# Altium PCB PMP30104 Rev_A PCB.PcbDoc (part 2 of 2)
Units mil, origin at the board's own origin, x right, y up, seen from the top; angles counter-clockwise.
Board outline 1835 x 2150 mil, 2 copper layers (Top Layer, Bottom Layer), stack 62 mil thick; 81 components, 42 nets, 182 pads, 76 vias.
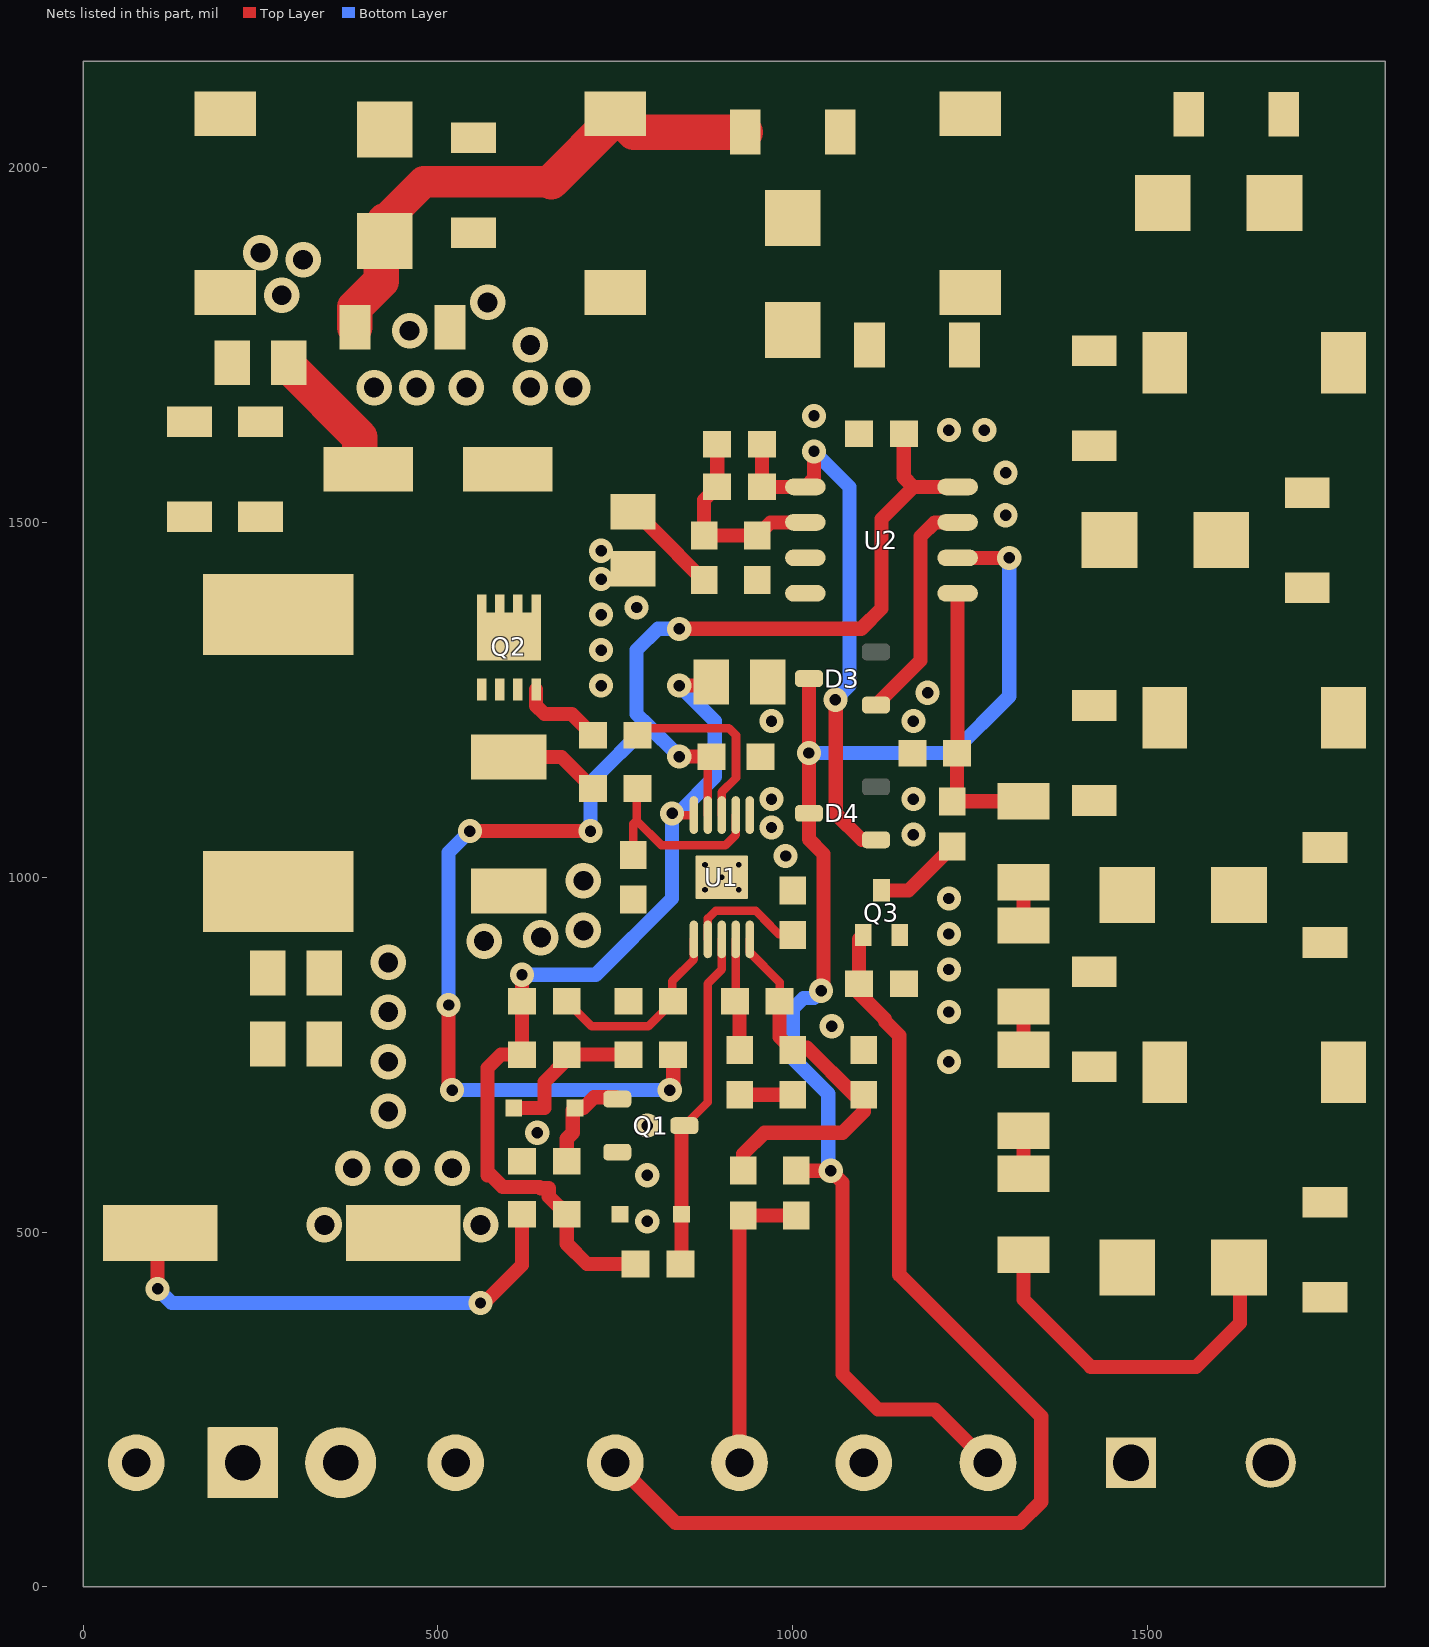
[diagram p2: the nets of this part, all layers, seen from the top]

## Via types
v1: diameter 34, hole 16, Top Layer to Bottom Layer, 47 vias
v2: diameter 50, hole 28, Top Layer to Bottom Layer, 24 vias
v3: diameter 19.68, hole 7.87, Top Layer to Bottom Layer, 5 vias

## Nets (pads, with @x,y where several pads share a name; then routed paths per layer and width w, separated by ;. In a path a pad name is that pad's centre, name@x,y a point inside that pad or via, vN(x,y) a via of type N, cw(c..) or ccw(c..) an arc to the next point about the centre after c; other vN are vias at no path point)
8VBIAS: C10.1 C15.2 R1.2 U1.9 U2.8 | length 2097.9
  Top Layer w12: U1.9@880.31,1087.6 880.31,1164.81 C10.1@885.5,1170
  Top Layer w20: v1(515,820) 515,705 v1(520,700) ; v1(545,1065) v1(715,1065) ; v1(826.57,700) 831.5,704.92 R1.2@831.5,750 ; v1(840,1170) C10.1@885.5,1170 ; v1(840,1350) 1096.38,1350 1124.92,1378.54 1124.92,1504.92 1170,1550 ; C15.2@1156.5,1625 1156.5,1563.5 1170,1550 ; U2.8@1232.28,1550 1170,1550
  Bottom Layer w20: v1(515,820) 515,1035 v1(545,1065) ; v1(520,700) v1(826.57,700) ; v1(715,1065) 715,1133.5 795.75,1214.25 ; v1(840,1170) 795.75,1214.25 ; v1(840,1350) 810,1350 780,1320 780,1230 795.75,1214.25
400V-420V: Q3.1 R24.1 TP8.1 | length 1554.8
  Top Layer w20: TP8.1@750,175 835,90 1320,90 1350,120 1350,240 1150,440 1150,777.04 1130,797.04 1130,800 1093.5,836.5 R24.1@1093.5,850 1093.5,912.6 Q3.1@1099.41,918.5
CS: D3.3 D4.3 R10.2 TP5.1 U2.6 | length 1932.7
  Top Layer w20: R10.2@1005,586.5 v1(1053.5,586.5) 1070,570 1070,300 1120,250 1200,250 TP5.1@1275,175 ; D3.3@1022.76,1280 v1(1022.76,1175) D4.3@1022.76,1090 1022.76,1053.57 1043.43,1032.9 1043.43,843.43 v1(1040,840) ; U2.6@1232.28,1450 v1(1305,1450)
  Bottom Layer w20: v1(1022.76,1175) 1225,1175 1305,1255 v1(1305,1450) ; v1(1040,840) 1030,830 1015,830 1000,815 1000,745 1050,695 1050,590 v1(1053.5,586.5)
GND: C1.2 C2.2 C4.2 C6.2 C7.2 C8.2 C9.2 C10.2 C14.1 C15.1 Cm6.1 D2.2 J1.2 J2.1 Q1.2 Q3.2 R3.1 R5.1 R13.1 R14.1 R21.2 R24.2 TP2.1 TP4.1 U1.6 U1.11 U2.3 U2.4
  other v1: 795,515 795,580 640,640 795,650 1220,740 1055,790 1220,810 1220,870 1220,920 1220,970 990,1030 1170,1060 970,1070 970,1110 1170,1110 970,1220 1170,1220 1190,1260 730,1270 730,1320 730,1370 780,1380 730,1420 730,1460 1300,1510 1300,1570 1220,1630 1270,1630 1030,1650
  other v2: 340,510 560,510 380,590 450,590 520,590 430,670 430,740 430,810 430,880 565,910 645,915 705,925 705,995 410,1690 470,1690 540,1690 460,1770 570,1810
  other v3: 876.38,982.28 923.62,982.28 900,1000 876.38,1017.72 923.62,1017.72
NetC1_1: C1.1 R7.1 U1.1 | length 279.7
  Top Layer w12: R7.1@681.5,825 716.5,790 796.5,790 C1.1@831.5,825 830,826.5 830,853.54 860.63,884.17 U1.1@860.63,912.4
NetC2_1: C2.1 U1.2 | length 168.4
  Top Layer w12: U1.2@880.31,912.4 880.24,941.96 891.75,952.98 947.62,952.98 959.28,941.32 959.28,940.72 980,920 998.5,920 C2.1@1000,918.5
NetC3_1: C3.1 C5.1 U1.4 | length 159.1
  Top Layer w12: C3.1@918.5,825 919.68,826.18 U1.4@919.68,912.4
  Top Layer w20: C3.1@918.5,825 925,818.5 C5.1@925,756.5
NetC3_2: C3.2 R5.2 R6.2 R8.1 U1.5 | length 551.9
  Top Layer w12: U1.5@939.37,912.4 939.37,894.17 981.5,852.05 C3.2@981.5,825
  Top Layer w20: R8.1@930,586.5 930,610 960,640 1070,640 1100,670 R5.2@1100,693.5 1086.5,693.5 1020,760 1003.5,760 R6.2@1000,756.5 981.5,775 C3.2@981.5,825
NetC4_1: C4.1 C6.1 C7.1 J1.1 L1.1 R9.2 TP1.1 | length 696
  Top Layer w20: C4.1@103.74,500 105,498.74 v1(105,420) ; v1(560,400) 565,400 618.5,453.5 R9.2@618.5,525
  Bottom Layer w20: v1(105,420) 125,400 v1(560,400)
NetC5_2: C5.2 R6.1 | length 75
  Top Layer w20: C5.2@925,693.5 R6.1@1000,693.5
NetC8_1: C8.1 R2.2 R4.2 R7.2 R9.1 U1.10 | length 1296.4
  Top Layer w12: v1(830,1090) 832.4,1087.6 U1.10@860.63,1087.6
  Top Layer w20: v1(618.5,862.5) R7.2@618.5,825 R2.2@618.5,750 588.98,750 570,731.02 570,580 574.66,580 591.36,563.3 643.2,563.3 644.8,561.7 656.19,561.7 656.19,550.31 R9.1@681.5,525 681.5,483.5 710,455 R4.2@778.5,455 ; v1(840,1270) 880,1270 C8.1@885,1275
  Bottom Layer w20: v1(618.5,862.5) 722.5,862.5 830,970 v1(830,1090) 838.54,1090 890,1141.46 890,1220 v1(840,1270)
NetC9_1: C9.1 R12.1 U1.7 | length 284.4
  Top Layer w12: C9.1@775,1031.5 775,1075 780,1080 ; R12.1@781.5,1125 780,1123.5 780,1080 ; U1.7@919.68,1087.6 919.68,1059.68 905,1045 815,1045 780,1080
NetC11_1: C11.1 C12.1 Cm1.1 Dm1.2 Lm1.1 R23.2
NetC11_2: C11.2 C12.2 C16.1 L1.2 Q2.5 Q2.6 Q2.7 Q2.8 Q2.9
NetC13_1: C13.1 C14.2 R19.1 R20.2 U2.2 | length 276.5
  Top Layer w20: C13.1@893.5,1600 R19.1@893.5,1550 875,1531.5 R20.2@875,1481.5 C14.2@950,1481.5 968.5,1500 U2.2@1017.72,1500
NetC13_2: C13.2 D4.1 R19.2 U2.1 | length 778
  Top Layer w20: C13.2@956.5,1600 R19.2@956.5,1550 U2.1@1017.72,1550 1030,1562.28 v1(1030,1600) ; v1(1060,1250) 1060.44,1249.56 1060.44,1089.56 1097.4,1052.6 D4.1@1117.24,1052.6
  Bottom Layer w20: v1(1030,1600) 1080,1550 1080,1270 v1(1060,1250)
NetC16_2: C16.2 R23.1 | length 196.2
  Top Layer w50: R23.1@290,1725 290,1720 390,1620 390,1586.57 C16.2@401.57,1575
NetCm1_2: Cm1.2 Cm2.1 Dm2.2 Lm2.1
NetCm2_2: Cm2.2 Cm3.1 Dm3.2 Lm3.1
NetCm3_2: Cm3.2 Cm4.1 Dm4.2 Lm4.1
NetCm4_2: Cm4.2 Cm5.1 Dm5.2 Lm5.1
NetCm5_2: Cm5.2 Dm6.2 Lm6.1
NetCm6_2: Cm6.2 Cm7.1 Dm1.1 Lm2.2 | length 745.2
  Top Layer w45: Dm1.1@425,1925 480,1980 660,1980
  Top Layer w50: Cm6.2@383.07,1775 383.07,1803.07 420,1840 Dm1.1@420,1891.26 ; Dm1.1@425,1896.26 Dm1.1@425,1925 ; 660,1980 750,2070 Lm2.2@750,2075.98 775.98,2050 Cm7.1@933.07,2050
NetCm7_2: Cm7.2 Cm8.1 Dm2.1 Lm3.2
NetCm8_2: Cm8.2 Cm9.1 Dm3.1 Lm4.2
NetCm9_2: Cm9.2 Cm10.1 Dm4.1 Lm5.2
NetCm10_2: Cm10.2 Cm11.1 Dm5.1 Lm6.2
NetCm11_2: Cm11.2 Dm6.1 J2.2 R18.1 | length 511.6
  Top Layer w20: R18.1@1325,467.91 1325,405 1420,310 1568.15,310 1630,371.85 1630,448.74 Dm6.1@1628.74,450
NetD1_1: D1.1 R1.1 R2.1 | length 218.4
  Top Layer w20: D1.1@606.69,675 650,675 650,711.47 681.5,742.97 R2.1@681.5,750 R1.1@768.5,750
NetD1_2: D1.2 Q1.1 R3.2 | length 146.6
  Top Layer w20: R3.2@681.5,600 681.5,631.5 690,640 690,671.69 D1.2@693.31,675 705,675 720,690 750.16,690 Q1.1@752.76,687.4
NetD2_1: D2.1 Q1.3 R4.1 U1.3 | length 481.6
  Top Layer w12: Q1.3@843.31,646.06 Q1.3@847.24,650 880,682.76 880,850 900,870 U1.3@900,912.4
  Top Layer w20: R4.1@841.5,455 843.31,456.81 D2.1@843.31,525 Q1.3@843.31,646.06
NetD3_1: D3.1 U2.7 | length 324
  Top Layer w20: D3.1@1117.24,1242.6 1180,1305.35 1180,1480 1200,1500 U2.7@1232.28,1500
NetLm1_2: Lm1.2 R20.1 R21.1 | length 140.5
  Top Layer w20: R21.1@775,1515 778.5,1515 838.3,1455.2 838.3,1454.36 874.15,1418.5 R20.1@875,1418.5
  other v2: 630,1690 690,1690 630,1750 280,1820 310,1870 250,1880
NetQ2_1: Q2.1 Q2.2 Q2.3 R12.2 R13.2 | length 136.9
  Top Layer w20: R13.2@600,1169.49 674.02,1169.49 R12.2@718.5,1125
NetQ2_4: Q2.4 R11.2 | length 120.2
  Top Layer w20: Q2.4@638.39,1264.47 638.39,1241.61 650,1230 688.5,1230 R11.2@718.5,1200
NetQ3_3: Q3.3 R22.1 | length 125.7
  Top Layer w20: Q3.3@1125,981.5 1162.99,981.5 R22.1@1225,1043.5
NetR8_2: R8.2 R10.1 TP3.1 | length 425.6
  Top Layer w20: TP3.1@925,175 925,518.5 R8.2@930,523.5 R10.1@1005,523.5
NetR11_1: R11.1 U1.8 | length 267.5
  Top Layer w12: R11.1@781.5,1200 791.5,1210 910,1210 920,1200 920,1140 900,1120 U1.8@900,1087.6
NetR14_2: R14.2 R15.2 R22.2 U2.5 | length 395.9
  Top Layer w20: R22.2@1225,1106.5 R22.2@1225.59,1107.09 ; U2.5@1232.28,1400 1232.28,1175.79 R14.2@1231.5,1175 1231.5,1112.99 R22.2@1225.59,1107.09 ; R15.2@1325,1107.09 R22.2@1225.59,1107.09
NetR15_1: R15.1 R16.2 | length 60.8
  Top Layer w20: R16.2@1325,932.09 R15.1@1325,992.91
NetR16_1: R16.1 R17.2 | length 60.8
  Top Layer w20: R17.2@1325,757.09 R16.1@1325,817.91
NetR17_1: R17.1 R18.2 | length 60.8
  Top Layer w20: R18.2@1325,582.09 R17.1@1325,642.91
pads on no net: D3.2 D4.2

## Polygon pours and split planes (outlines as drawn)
NetCm11_2 on Top Layer "Top Layer-No Net 11" (solid, pour order 24): 1573.43,503.43 1590,520 1660,520 1690,490 1700,480 1790,480 1810,460 1810,130 1760,80 1645,80 1645,270 1573.43,330
NetCm5_2 on Top Layer "Top Layer-No Net 10" (solid, pour order 22): 1390,800 1570,800 1590,780 1590,570 1530,510 1530,421.5 1500,391.5 1418.5,391.5 1410,400 1390,420
NetCm10_2 on Top Layer "Top Layer-No Net 8" (solid, pour order 20): 1580,1010 1590,1020 1643.5,1020 1690,973.5 1690,970 1790,970 1810,950 1810,520 1800,510 1712.6,510 1702.6,520 1700,520 1700,570 1630,640 1630,650 1630,850 1580,910
NetCm4_2 on Top Layer "Top Layer-No Net 9" (solid, pour order 18): 1490,1270 1500,1280 1590,1280 1600,1270 1600,1080.12 1560.5,1040.62 1560.5,1033.5 1550,1023 1550,940 1540,930 1530,930 1510,910 1510,880 1470,840 1462.4,840 1390,840 1390,1190 1462.4,1190 1470,1190 1490,1210
NetCm9_2 on Top Layer "Top Layer-No Net 8" (solid, pour order 16): 1550,1510 1570,1530 1570,1533.5 1630,1533.5 1690,1473.5 1690,1470 1790,1470 1810,1450 1810,1020 1800,1010 1712.6,1010 1702.6,1020 1700,1020 1700,1070 1630,1140 1630,1150 1630,1350 1550,1430 1550,1440
NetCm3_2 on Top Layer "Top Layer-No Net 7" (solid, pour order 14): 1490,1800 1590,1800 1600,1790 1600,1780 1600,1610 1510,1520 1510,1430 1510,1380 1460,1330 1460,1230 1450,1220 1440,1220 1370,1220 1365,1225 1365,1655 1370,1660 1390,1660 1470,1660 1490,1680
NetCm8_2 on Top Layer "Top Layer-No Net 6" (solid, pour order 12): 1640,2120 1810,2120 1810,1520 1800,1510 1790,1510 1700,1510 1640,1570 1640,1580
NetCm2_2 on Top Layer "Top Layer-No Net 5" (solid, pour order 10): 1180,1910 1390,1910 1470,1990 1590,1990 1590,1850 1570,1830 1560,1830 1470,1830 1460,1820 1462.4,1817.6 1462.4,1710 1452.4,1700 1450,1700 1180,1700
NetCm7_2 on Top Layer "Top Layer-No Net 4" (solid, pour order 8): 1010,2130 1590,2130 1600,2120 1600,2112.4 1600,2037.6 1592.4,2030 1590,2030 1450,2030 1370,1950 1170,1950 1140,1950 1080,1890 960,1890 940,1910 940,1972 938,1974 994,2030 1000,2036 1000,2120
NetCm1_2 on Top Layer "Top Layer-No Net 3" (solid, pour order 6): 520,1930 870,1930 990,1810 1100,1810 1130,1810 1140,1800 1140,1790 1140,1710 1130,1700 930,1700 850,1780 690,1780 600,1870 520,1870
NetC11_1 on Top Layer "Top Layer-No Net 2" (solid, pour order 4): 20,2130 610,2130 609.06,2129.06 609.06,2020 560,2020 470,2020 440,1990 350,1990 290,1930 150,1930 130,1910 130,1780 140,1770 145,1765 230,1765 240,1755 240,1750 250,1740 250,1670 280,1670 290,1660 287.4,1657.4 287.4,1610 20,1610
NetC11_2 on Top Layer "Top Layer-No Net 1" (solid, pour order 2): 30,1580 310,1580 310,1530 320,1520 480,1520 490,1530 490,1540 490,1630 500,1640 700,1640 700,1300 533.07,1300 503.07,1270 500,1270 510,1260 510,1140 490,1120 30,1120
NetC4_1 on Top Layer "Top Layer-No Net" (solid, pour order 0): 10,100 280,100 280,120 280,900 280,920 430,920 460,950 460,1060 440,1080 440,1090 10,1090
NetQ2_1 on Top Layer "Top Layer-No Net 12" (solid, pour order 26): 533.07,1270 543.07,1280 550,1280 620,1280 620,1230 650,1200 660,1200 670,1200 680,1190 680,1180 706.46,1153.54 740,1153.54 740,1096.46 723.54,1080 710,1080 540,1080 530,1090 530,1100 530,1270
NetLm1_2 on Top Layer "Top Layer-No Net 13" (solid, pour order 28): 820,1510 840,1530 840,1680 840,1720 840,1750 830,1760 820,1760 670,1760 650,1780 620,1780 600,1760 600,1750 600,1690 600,1660 615.24,1660 710,1660 720,1650 720,1520 730,1510 735,1510
NetLm1_2 on Top Layer "Top Layer-No Net 14" (solid, pour order 30): 150,1910 310,1910 340,1880 340,1800 330,1790 320,1790 150,1790
GND on Top Layer "Top Layer-No Net 15" (solid, pour order 34): 430,1790 490,1850 520,1850 590,1850 620,1820 620,1800 590,1770 580,1760 580,1750 580,1670 570,1660 490,1660 470,1640 430,1640 420,1640 380,1680 380,1720 420,1720 422.4,1720 430,1727.6
GND on Top Layer "Top Layer-No Net 16" (solid, pour order 36): 1320,1670 1320,920 1250,840 1250,510 1250,408.15 1410,248.15 1410,72.99 1354.53,17.52 312.48,17.52 312.48,905 445,905 490,950 490,1100 490,1670
NetLm1_2 on Bottom Layer "Bottom Layer-No Net" (solid, pour order 32): 160,1900 160,1780 175,1765 190,1765 195,1760 370,1760 460,1850 470,1850 550,1850 590,1810 590,1695.24 590,1660 610,1660 690,1660 720,1660 720,1690 720,1700 720,1860 600,1980 250,1980 220,1980 160,1920 160,1910
GND on Bottom Layer "Bottom Layer-No Net 1" (solid, pour order 38): 25.49,2124.51 30.98,2130 1400,2130 1810,2130 1810,390 1710,290 1630,290 1560,290 1530,260 1510,240 1510,45.08 1484.92,20 1480,20 1470,30 20,30

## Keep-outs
Keep-Out Layer:
  text ".Layer_Name" at 577,-858.49 h60

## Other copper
Top Layer:
  text ".Layer_Name" at 2095,1955 h60
Bottom Layer:
  text ".Layer_Name" at 2110,1680 h60

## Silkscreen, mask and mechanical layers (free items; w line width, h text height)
Top Overlay:
  text ".Layer_Name" at 577,-858.49 h60
Bottom Overlay:
  text ".Layer_Name" at 577,-858.49 h60
Top Paste:
  text ".Layer_Name" at 577,-858.49 h60
Bottom Paste:
  text ".Layer_Name" at 577,-858.49 h60
Top Solder:
  text ".Layer_Name" at 577,-858.49 h60
  text ".Layer_Name" at 577,-858.49 h60
Bottom Solder:
  text "A" at 675,310 h60
  text "'.PRJ_Number'.PCB_Rev-" at 1200,305 h108.27
  text ".Layer_Name" at 577,-858.49 h60
Drill Guide:
  text ".Layer_Name" at 577,-858.49 h60
M1 Board Outline:
  the board outline again, w10
  text ".Layer_Name" at 2110,2085 h60
M2 Board Dimensions:
  rectangle: 0,-275 125,-150
  rectangle: 125,-400 500,-275
  lines w7: 0,-275 1000,-275 ; 125,-400 125,-150 ; 250,-400 250,-150 ; 500,-400 500,-150 ; 750,-400 750,-150 ; 0,-400 1000,-400 1000,-150 0,-150 0,-400
  text ".Layer_Name" at 2120,1805 h60
M3 3D STEP Top:
  text ".Layer_Name" at 577,-858.49 h60
M4 3D STEP Bottom:
  text ".Layer_Name" at 577,-858.49 h60
M5 Assembly Top:
  lines w10: -292,-930.17 6308,-930.17 ; -292,-726.83 6310,-726.83 ; -292,-523.5 -292,-1133.5 3713,-1133.5 6310,-1133.5 6310,-523.5 -291.5,-523.5 -291.5,-1133.5 1284,-1133.5 ; 2173,-1133.5 2173,-523.5 ; 3440,-726.83 3440,-523.5 ; 4280,-726.83 4280,-523.5 ; 4902,-1140 4902,-937.17
  text "COMPONENTS MARKED 'DNP' SHOULD NOT BE POPULATED." at 1153.5,-318.5 h60
  text "ASSEMBLY VARIANT:" at 1153,-434 h60
  text ".VariantName" at 2189,-434 h60
  text "BOARD #:" at 2248,-655.67 h60
  text ".PRJ_Number" at 2793.5,-655.67 h60
  text "REV:" at 3638,-655.67 h60
  text ".PCB_Rev" at 3929.5,-655.67 h60
  text "SVN REV:" at 4476,-655.67 h60
  text ".VersionControl_RevNumber" at 4982,-655.67 h60
  text "TID #:" at 2248,-859 h60
  text ".TID" at 2793.5,-859 h60
  text "PLOT NAME =" at -228.5,-1064.34 h60
  text ".plot_File_Name" at 577,-1064.34 h60
  text "GENERATED    :" at 2250,-1064.34 h60
  text ".Print_Date" at 3119.5,-1064.34 h60
  text ".Print_Time" at 3848.5,-1064.34 h60
  text "TEXAS INSTRUMENTS" at 5113,-1064.34 h60
M6 Assembly Bottom:
  lines w10: -292.5,-727.33 6309.5,-727.33 ; -290.5,-930.67 6309.5,-930.67 ; 1115.5,-1140.5 1115.5,-937.67 ; 1737.5,-727.33 1737.5,-524 ; 2577.5,-727.33 2577.5,-524 ; 3844.5,-1134 3844.5,-524 ; 4733.5,-1134 6309,-1134 6309,-524 -292.5,-524 -292.5,-1134 2304.5,-1134 6309.5,-1134 6309.5,-524
  text "COMPONENTS MARKED 'DNP' SHOULD NOT BE POPULATED." at 6102,-318 h60
  text ".VariantName" at 5058,-434 h60
  text "ASSEMBLY VARIANT:" at 6097,-434 h60
  text ".VersionControl_RevNumber" at 1035.5,-656.17 h60
  text ".PCB_Rev" at 2088,-656.17 h60
  text "REV:" at 2379.5,-656.17 h60
  text ".PRJ_Number" at 3224,-656.17 h60
  text "BOARD #:" at 3769.5,-656.17 h60
  text "PCB VIEWED FROM BOTTOM SIDE" at 6246,-656.17 h60
  text ".TID" at 3224,-859.5 h60
  text "TID #:" at 3769.5,-859.5 h60
  text "TEXAS INSTRUMENTS" at 904.5,-1064.84 h60
  text ".Print_Time" at 2169,-1064.84 h60
  text ".Print_Date" at 2898,-1064.84 h60
  text "GENERATED    :" at 3767.5,-1064.84 h60
  text ".plot_File_Name" at 5440.5,-1064.84 h60
  text "PLOT NAME =" at 6246,-1064.84 h60
M9 Title Sheet:
  drawing of 57 lines, arcs and shapes, not listed
  text "1" at 739.84,8036.5 h70
  text "2" at 3235.5,8036.5 h70
  text "3" at 5724.84,8036.5 h70
  text "4" at 8231.51,8036.5 h70
  text "5" at 10730.5,8036.5 h70
  text "6" at 13235.5,8036.5 h70
  text "A" at -416.5,6893.5 h70
  text "A" at 14383.5,6893.5 h70
  text "B" at -416.5,4513.5 h70
  text "B" at 14383.5,4513.5 h70
  text "C" at -416.5,2138.5 h70
  text "C" at 14383.5,2138.5 h70
  text "PROJECT TITLE:" at 11343.5,277.5 h45
  text ".PRJ_Title" at 11393.5,144.17 h70
  text "DESIGNED FOR:" at 11343.5,-23.5 h45
  text ".PRJ_Customer" at 11393.5,-163.5 h70
  text "D" at -416.5,-231.5 h70
  text "D" at 14383.5,-231.5 h70
  text "FILE NAME:" at 11343.5,-323.5 h45
  text ".PCB_File_Name_No_Path" at 11393.5,-443.5 h70
  text "Texas Instruments (TI) and/or its licensors do not warrant the accuracy or completeness of this specification" at 6374,-605.34 h45
  text "ENGINEER:" at 11343.5,-613.5 h45
  text "LAYOUT BY:" at 12848.5,-613.5 h45
  text "or any information contained therein. TI and/or its licensors do not warrant that this design will meet" at 6329.01,-718 h45
  text ".PRJ_Engineer" at 11393.5,-768.49 h70
  text ".PCB_Layout" at 12899,-768.49 h70
  text "the specifications, will be suitable for your application or fit for any particular purpose, or will operate in" at 6329.01,-830.67 h45
  text ".Layer_Name" at 577,-858.49 h60
  text "ALTIUM DESIGNER VERSION:" at 12848.5,-923.5 h45
  text "an implementation. TI and/or its licensors do not warrant that the design is production worthy. You should" at 6329.01,-943.33 h45
  text "completely validate and test your design implementation to confirm the system functionality for your application." at 6374,-1056 h45
  text ".print_Scale" at 11393.5,-1056.83 h70
  text ".Application_BuildNumber" at 12899,-1056.83 h70
  text "1" at 739.84,-1263.5 h70
  text "2" at 3235.5,-1263.5 h70
  text "3" at 5724.84,-1263.5 h70
  text "4" at 8231.51,-1263.5 h70
  text "5" at 10730.5,-1263.5 h70
  text "6" at 13235.5,-1263.5 h70
M10 Fab Notes:
  drawing of 173 lines, arcs and shapes, not listed
  text "DESIGN INFORMATION" at 12378.02,6201 h60
  text "MIN. TRACK WIDTH:" at 11733.46,6021 h60
  text "8" at 12829.7,6021 h60
  text "MIL" at 12984.46,6021 h60
  text "MIN. CLEARANCE:" at 11733.46,5889 h60
  text "0.2" at 12769.7,5889 h60
  text "mm" at 12984.46,5889 h60
  text "MIN. VIA PAD SIZE:" at 11733.46,5757 h60
  text "24" at 12799.71,5757 h60
  text "MIL" at 12984.46,5757 h60
  text "0.05mm (2MIL)" at 12428.46,5615.29 h60
  text "MINIMUM ANNULAR RING" at 11404.23,5611 h60
  text "EXTERNAL" at 13136.46,5611 h60
  text "PER" at 11604.23,5493 h60
  text "IPC-D-275 CLASS 2 LEVEL C" at 11824.23,5493 h60
  text "MIL, HOLES" at 13312.46,5380.71 h60
  text "+/-" at 12920,5380 h60
  text "+/-" at 13774,5380 h60
  text "REGISTRATION TOLERANCES:" at 11404.23,5375 h60
  text "METAL" at 12604,5375 h60
  text "5" at 13180.2,5375 h60
  text "3" at 14013.2,5375 h60
  text "MIL" at 14129.46,5375 h60
  text "+/-" at 13774,5262 h60
  text "HOLE SIZE TOLERANCE (UNLESS OTHERWISE SPECIFIED):" at 11404.23,5257 h60
  text "3" at 14013.2,5257 h60
  text "MIL" at 14129.46,5257 h60
  text "MATERIAL:" at 11329.46,5047.54 h60
  text "FR-4 High Tg" at 12315.9,4907.21 h60
  text "FR-408" at 11750.46,4898.64 h60
  text "OTHER" at 13238.46,4898.64 h60
  text "X" at 12161,4895 h60
  text "62 MIL (1.6mm) +/-10%" at 12070.56,4735.92 h60
  text "THICKNESS:" at 11404.23,4731.64 h60
  text "X" at 11942.4,4731.64 h60
  text "OTHER" at 13355.46,4731.64 h60
  text "TOLERANCE:" at 11404.23,4573.64 h60
  text "X" at 12243.53,4573.64 h60
  text "ANSI IPC-6012 TYPE 3 CLASS 2" at 12430.48,4573.64 h60
  text "OTHER +/-" at 12430.46,4417.64 h60
  text "BOW & TWIST:" at 11404.23,4260.64 h60
  text "X" at 12243.53,4260.64 h60
  text "ANSI IPC-6012 TYPE 3 CLASS 2" at 12430.48,4260.64 h60
  text "OTHER +/-" at 12430.46,4102.13 h60
  text "DRILLING:" at 11329.46,3963.64 h60
  text "REFERENCE:" at 11404.23,3846.64 h60
  text "X" at 12052.46,3846.64 h60
  text "AS SHOWN" at 12239.46,3846.64 h60
  text "X" at 12953.46,3846.64 h60
  text "NC_DRILL FILES" at 13090.46,3846.64 h60
  text "PTH COPPER THICKNESS:" at 11404.23,3688.64 h60
  text "X" at 12534.46,3688.64 h60
  text "20-30 um" at 12671.46,3688.64 h60
  text "OTHER" at 13388.46,3688.64 h60
  text "BOARD FINISH:" at 11329.46,3529.64 h60
  text "SILKSCREEN:" at 11484.68,3411.64 h60
  text "X" at 12433.46,3411.64 h60
  text "TOP" at 12559.46,3411.64 h60
  text "X" at 12943.46,3411.64 h60
  text "BOTTOM" at 13070.46,3411.64 h60
  text "SILKSCREEN COLOR:" at 11484.68,3244.64 h60
  text "X" at 12432.42,3244.64 h60
  text "WHITE" at 12559.46,3244.64 h60
  text "OTHER" at 13070.46,3244.64 h60
  text "X" at 12563.42,3085.44 h60
  text "GREEN" at 12690.46,3085.44 h60
  text "OTHER" at 13308.46,3085.44 h60
  text "SOLDER RESIST COLOR:" at 11484.68,3074.64 h60
  text "X" at 12563.42,2915.44 h60
  text "MATTE" at 12690.46,2915.44 h60
  text "SEMI-GLOSS" at 13308,2914.8 h60
  text "IMMERSION GOLD (ENIG)" at 12390.46,2726.92 h60
  text "ENEPIG" at 13728,2723.64 h60
  text "SURFACE FINISH:" at 11329.46,2722.64 h60
  text "X" at 12203.51,2722.64 h60
  text "IMM. TIN/SILVER OR EQUIV" at 11659,2565.64 h60
  text "OTHER" at 13090.46,2565.64 h60
  text "ARRAY/PANEL:" at 11329.46,2386.64 h60
  text "CUT AND TRIM PER M1 BOARD OUTLINE" at 12390.46,2382.35 h60
  text "N.C. ROUTE" at 12390.46,2230.64 h60
  text "X" at 13069.46,2230.64 h60
  text "V. SCORE" at 13256.46,2230.64 h60
  text "CERTIFICATION:" at 11329.46,2093.64 h60
  text "MATERIALS AND WORKMANSHIP FOR ALL PCBS" at 12054.46,2093.64 h60
  text "TO MEET OR EXCEED THE REQUIREMENTS OF:" at 12054.46,1995.64 h60
  text "X" at 11680.96,1859.13 h60
  text "ANSI IPC-A-600F CLASS ->" at 11819.96,1859.13 h60
  text "X" at 13459.02,1859.13 h60
  text "2" at 13577.96,1859.14 h60
  text "1" at 13262.96,1857.64 h60
  text "3" at 13931.96,1857.64 h60
  text "X" at 12495.02,1699.64 h60
  text "RoHS" at 12631.96,1699.64 h60
  text "OTHER" at 13276.36,1699.64 h60
  text "PER ORDER" at 13673.42,1699.64 h60
  text "ALL BOARDS MUST MEET OR EXCEED UL94-V0 REQUIREMENTS." at 11357,1534 h60
  text "PCB MUST BEAR THE UL94V-0 UL REGISTERED MATERIAL ID NUMBER" at 11357,1414 h60
  text "ADDITIONAL REQUIREMENTS:" at 11329.46,1240.64 h60
  text "MICROSECTION:" at 11404.23,1125.64 h60
  text "YES" at 12309.96,1125.64 h60
  text "REQUIRED" at 13171.46,969.49 h60
  text "BARE BOARD ELEC. TEST:" at 11404.23,966.64 h60
  text "NONE" at 12709.96,966.64 h60
  text "X" at 13044.46,966.64 h60
  text "PER ORDER" at 13763.46,966.64 h60
  text ".Layer_Name" at 577,-858.49 h60
M11 Gerber Information:
  lines w10: -292,-930.17 6308,-930.17 ; -292,-726.83 6310,-726.83 ; -292,-523.5 -292,-1133.5 3713,-1133.5 6310,-1133.5 6310,-523.5 -291.5,-523.5 -291.5,-1133.5 1284,-1133.5 ; 2173,-1133.5 2173,-523.5 ; 3440,-726.83 3440,-523.5 ; 4280,-726.83 4280,-523.5 ; 4902,-1140 4902,-937.17
  text "BOARD #:" at 2248,-655.67 h60
  text ".PRJ_Number" at 2793.5,-655.67 h60
  text "REV:" at 3638,-655.67 h60
  text ".PCB_Rev" at 3929.5,-655.67 h60
  text "SVN REV:" at 4476,-655.67 h60
  text ".VersionControl_RevNumber" at 4982,-655.67 h60
  text "LAYER NAME =" at -228.5,-858.49 h60
  text "TID #:" at 2248,-859 h60
  text ".TID" at 2793.5,-859 h60
  text "PLOT NAME =" at -228.5,-1064.34 h60
  text ".plot_File_Name" at 577,-1064.34 h60
  text "GENERATED    :" at 2250,-1064.34 h60
  text ".Print_Date" at 3119.5,-1064.34 h60
  text ".Print_Time" at 3848.5,-1064.34 h60
  text "TEXAS INSTRUMENTS" at 5113,-1064.34 h60
M12 Stackup:
  drawing of 191 lines, arcs and shapes, not listed
  text "Layer" at 9790.34,7830 h60
  text "Name" at 10200.26,7830 h60
  text "Material" at 11130,7830 h60
  text "Thickness" at 11989.77,7830 h60
  text "Constant" at 12639.6,7830 h60
  text "Board Layer Stack" at 13209.46,7830 h60
  text "1" at 9790.34,7710 h60
  text "Top Overlay" at 10200.26,7710 h60
  text "2" at 9790.34,7590 h60
  text "Top Solder" at 10200.26,7590 h60
  text "Solder Resist" at 11130,7590 h60
  text "0.40mil" at 11989.77,7590 h60
  text "3.5" at 12639.6,7590 h60
  text "3" at 9790.34,7470 h60
  text "Top Layer" at 10200.26,7470 h60
  text "Copper" at 11130,7470 h60
  text "1.40mil" at 11989.77,7470 h60
  text "4" at 9790.34,7350 h60
  text "Dielectric1" at 10200.26,7350 h60
  text "FR-4" at 11130,7350 h60
  text "59.20mil" at 11989.77,7350 h60
  text "4.8" at 12639.6,7350 h60
  text "5" at 9790.34,7230 h60
  text "Bottom Layer" at 10200.26,7230 h60
  text "Copper" at 11130,7230 h60
  text "1.40mil" at 11989.77,7230 h60
  text "6" at 9790.34,7110 h60
  text "Bottom Solder" at 10200.26,7110 h60
  text "Solder Resist" at 11130,7110 h60
  text "0.40mil" at 11989.77,7110 h60
  text "3.5" at 12639.6,7110 h60
  text "7" at 9790.34,6990 h60
  text "Bottom Overlay" at 10200.26,6990 h60
  text ".Layer_Name" at 577,-858.49 h60
M13 Component Bodies Top:
  text ".Layer_Name" at 577,-858.49 h60
M14 Component Bodies Bottom:
  text ".Layer_Name" at 577,-858.49 h60
M15 Courtyards Top:
  text ".Layer_Name" at 577,-858.49 h60
M16 Courtyards Bottom:
  text ".Layer_Name" at 577,-858.49 h60
Drill Drawing:
  lines w10: 5336.14,2616.13 5363.8,2629.96 5391.46,2616.13 5377.63,2643.78 5391.46,2671.44 5363.8,2657.61 5336.14,2671.44 5349.97,2643.78 5336.14,2616.13 ; 5336.14,2795.9 5391.46,2795.9 5363.8,2740.59 5336.14,2795.9 ; 5336.14,2865.04 5391.46,2865.04 5391.46,2920.36 5336.14,2920.36 5336.14,2865.04 ; 5336.14,2989.5 5336.14,3003.33 5349.97,3017.16 5336.14,3030.99 5336.14,3044.82 5349.97,3044.82 5363.8,3030.99 5377.63,3044.82 5391.46,3044.82 5391.46,3030.99 5377.63,3017.16 5391.46,3003.33 5391.46,2989.5 5377.63,2989.5 5363.8,3003.33 5349.97,2989.5 5336.14,2989.5 ; 5336.14,3127.79 5349.97,3127.79 5349.97,3113.96 5377.63,3113.96 5377.63,3127.79 5391.46,3127.79 5391.46,3155.45 5377.63,3155.45 5377.63,3169.28 5349.97,3169.28 5349.97,3155.45 5336.14,3155.45 5336.14,3127.79 ; 5336.14,3252.25 5349.97,3252.25 5363.8,3238.42 5377.63,3252.25 5391.46,3252.25 5377.63,3266.08 5391.46,3279.91 5377.63,3279.91 5363.8,3293.74 5349.97,3279.91 5336.14,3279.91 5349.97,3266.08 5336.14,3252.25
  lines w12: 5286,2578.79 8518.76,2578.79 ; 5286,3325.54 8518.76,3325.54 ; 5624.17,2454.33 5624.17,3450 ; 5956.28,2454.33 5956.28,3450 ; 6593.29,2454.33 6593.29,3450 ; 6852.64,2454.33 6852.64,3450 ; 7228.06,2454.33 7228.06,3450 ; 7951.91,2454.33 7951.91,3450 ; 5286,2454.33 8518.76,2454.33 8518.76,3450 5286,3450 5286,2454.33
  text "Symbol" at 5360.68,3362.88 h72
  text "Quantity" at 5661.51,3362.88 h72
  text "Finished Hole Size" at 5993.62,3362.88 h72
  text "Plated" at 6630.62,3362.88 h72
  text "Hole Type" at 6889.98,3362.88 h72
  text "Drill Layer Pair" at 7265.4,3362.88 h72
  text "Hole Tolerance" at 7989.25,3362.88 h72
  text "5" at 5661.51,3238.42 h60
  text "7.87mil (0.200mm)" at 5993.62,3238.42 h60
  text "PTH" at 6630.62,3238.42 h60
  text "Round" at 6889.98,3238.42 h60
  text "Top Layer - Bottom Layer" at 7265.4,3238.42 h60
  text "47" at 5661.51,3113.96 h60
  text "16.00mil (0.406mm)" at 5993.62,3113.96 h60
  text "PTH" at 6630.62,3113.96 h60
  text "Round" at 6889.98,3113.96 h60
  text "Top Layer - Bottom Layer" at 7265.4,3113.96 h60
  text "24" at 5661.51,2989.5 h60
  text "28.00mil (0.711mm)" at 5993.62,2989.5 h60
  text "PTH" at 6630.62,2989.5 h60
  text "Round" at 6889.98,2989.5 h60
  text "Top Layer - Bottom Layer" at 7265.4,2989.5 h60
  text "6" at 5661.51,2865.04 h60
  text "40.00mil (1.016mm)" at 5993.62,2865.04 h60
  text "PTH" at 6630.62,2865.04 h60
  text "Round" at 6889.98,2865.04 h60
  text "Top Layer - Bottom Layer" at 7265.4,2865.04 h60
  text "2" at 5661.51,2740.59 h60
  text "50.00mil (1.270mm)" at 5993.62,2740.59 h60
  text "PTH" at 6630.62,2740.59 h60
  text "Round" at 6889.98,2740.59 h60
  text "Top Layer - Bottom Layer" at 7265.4,2740.59 h60
  text "2" at 5661.51,2616.13 h60
  text "51.18mil (1.300mm)" at 5993.62,2616.13 h60
  text "PTH" at 6630.62,2616.13 h60
  text "Round" at 6889.98,2616.13 h60
  text "Top Layer - Bottom Layer" at 7265.4,2616.13 h60
  text "86 Total" at 5661.51,2491.67 h60
  text ".Layer_Name" at 577,-858.49 h60
M17 Embedded Cavity:
  text ".Layer_Name" at 577,-858.49 h60
M18 Embedded Assembly:
  text ".Layer_Name" at 577,-858.49 h60
M19 Embedded Keepout:
  text ".Layer_Name" at 577,-858.49 h60

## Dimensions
0,-400 to 1000,-400 on M2 Board Dimensions
0,0 to 0,2150 on M2 Board Dimensions
0,0 to 1835,0 on M2 Board Dimensions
